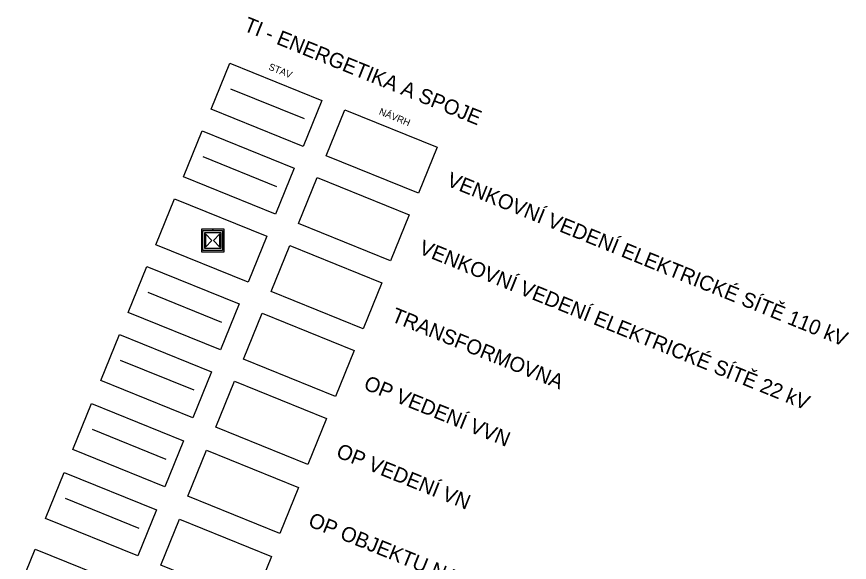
# Model space of a CAD drawing. Extents: x -522754 to -518969, y -1191121 to -1188171.
# Drawn here: x -519807 to -518969, y -1189893 to -1189344 of the extents above; entities that cross this region are included whole.
import ezdxf

# ---------------------------------------------------------------- set-up
doc = ezdxf.new("R2010")
doc.units = 0
for name, color, linetype in [('elved_110_s', 7, 'Continuous'), ('elved_22_s', 7, 'Continuous'), ('Implicitní', 7, 'Continuous'), ('ložisk_nerost', 7, 'Continuous'), ('OP_OelVN_s', 7, 'Continuous'), ('OP_VN_s', 7, 'Continuous'), ('OP_VVN_s', 7, 'Continuous'), ('plyn_VTL_s', 7, 'Continuous')]:
    doc.layers.add(name, color=color, linetype=linetype)

msp = doc.modelspace()

# ---------------------------------------------------------------- linework, layer by layer
at = {"layer": 'elved_110_s'}
msp.add_line((-519592.12, -1189416.32), (-519517.98, -1189446.37), dxfattribs=at)
at = {"layer": 'elved_22_s'}
msp.add_line((-519619.99, -1189484.54), (-519545.85, -1189514.59), dxfattribs=at)
at = {"layer": 'Implicitní'}
for points in [[(-519592.95, -1189390.41), (-519500.27, -1189427.97), (-519519.05, -1189474.31), (-519611.73, -1189436.75)], [(-519477.1, -1189437.37), (-519384.42, -1189474.93), (-519403.2, -1189521.27), (-519495.88, -1189483.7)], [(-519620.81, -1189458.64), (-519528.14, -1189496.2), (-519546.92, -1189542.54), (-519639.59, -1189504.98)], [(-519504.97, -1189505.59), (-519412.29, -1189543.15), (-519431.07, -1189589.49), (-519523.75, -1189551.93)], [(-519648.5, -1189526.95), (-519555.82, -1189564.51), (-519574.6, -1189610.85), (-519667.28, -1189573.28)], [(-519532.65, -1189573.9), (-519439.97, -1189611.46), (-519458.75, -1189657.8), (-519551.43, -1189620.24)], [(-519676.36, -1189595.17), (-519583.69, -1189632.73), (-519602.47, -1189679.07), (-519695.15, -1189641.51)], [(-519560.52, -1189642.12), (-519467.84, -1189679.68), (-519486.62, -1189726.02), (-519579.3, -1189688.46)], [(-519704.05, -1189663.48), (-519611.37, -1189701.04), (-519630.15, -1189747.38), (-519722.83, -1189709.82)], [(-519588.2, -1189710.43), (-519495.52, -1189747.99), (-519514.3, -1189794.33), (-519606.98, -1189756.77)], [(-519732.22, -1189732.99), (-519639.54, -1189770.55), (-519658.32, -1189816.89), (-519751, -1189779.32)], [(-519616.37, -1189779.94), (-519523.69, -1189817.5), (-519542.48, -1189863.84), (-519635.15, -1189826.28)], [(-519759.54, -1189802.56), (-519666.87, -1189840.12), (-519685.65, -1189886.46), (-519778.32, -1189848.9)], [(-519643.7, -1189849.51), (-519551.02, -1189887.07), (-519569.8, -1189933.41), (-519662.48, -1189895.85)], [(-519788.72, -1189879.61), (-519696.04, -1189917.17), (-519714.82, -1189963.51), (-519807.5, -1189925.95)]]:
    msp.add_lwpolyline(points, close=True, dxfattribs=at)
at = {"layer": 'ložisk_nerost'}
for p, q in [((-519610.89, -1189569.01), (-519617.5, -1189562.39)), ((-519602.85, -1189562.39), (-519609.47, -1189569.01)), ((-519617.5, -1189568.97), (-519618.2, -1189568.97)), ((-519618.2, -1189569.01), (-519617.5, -1189569.01)), ((-519617.5, -1189575.63), (-519610.89, -1189569.01)), ((-519609.47, -1189569.01), (-519602.86, -1189575.63)), ((-519602.16, -1189568.97), (-519602.86, -1189568.97)), ((-519602.86, -1189569.01), (-519602.16, -1189569.01))]:
    msp.add_line(p, q, dxfattribs=at)
for points in [[(-519610.21, -1189557.57), (-519621.62, -1189557.57), (-519621.62, -1189580.45), (-519598.74, -1189580.45), (-519598.74, -1189557.57), (-519610.18, -1189557.57)], [(-519610.18, -1189558.97), (-519600.15, -1189558.98), (-519600.15, -1189579.04), (-519620.21, -1189579.04), (-519620.21, -1189558.97), (-519610.21, -1189558.97)], [(-519620.21, -1189558.98), (-519600.15, -1189558.98), (-519600.15, -1189579.04), (-519620.21, -1189579.04), (-519620.21, -1189558.98)], [(-519618.2, -1189568.97), (-519618.2, -1189560.99), (-519610.15, -1189560.99)], [(-519617.5, -1189562.39), (-519617.5, -1189568.97)], [(-519610.21, -1189558.97), (-519610.21, -1189557.57)], [(-519610.18, -1189557.57), (-519610.18, -1189558.97)], [(-519610.15, -1189560.99), (-519602.16, -1189560.99), (-519602.16, -1189568.97)], [(-519602.86, -1189568.97), (-519602.85, -1189562.39)], [(-519610.15, -1189577.03), (-519618.2, -1189577.03), (-519618.2, -1189569.01)], [(-519617.5, -1189569.01), (-519617.5, -1189575.63)], [(-519602.16, -1189569.01), (-519602.16, -1189577.03), (-519610.15, -1189577.03)], [(-519602.86, -1189575.63), (-519602.86, -1189569.01)]]:
    msp.add_lwpolyline(points, dxfattribs=at)
at = {"layer": 'OP_OelVN_s'}
msp.add_line((-519731.4, -1189758.89), (-519657.26, -1189788.94), dxfattribs=at)
at = {"layer": 'OP_VN_s'}
msp.add_line((-519703.23, -1189689.38), (-519629.09, -1189719.43), dxfattribs=at)
at = {"layer": 'OP_VVN_s'}
msp.add_line((-519675.54, -1189621.07), (-519601.4, -1189651.12), dxfattribs=at)
at = {"layer": 'plyn_VTL_s'}
msp.add_line((-519758.72, -1189828.46), (-519684.58, -1189858.51), dxfattribs=at)

# ---------------------------------------------------------------- texts
at = {"layer": 'Implicitní'}
for s, height, p in [('TI - ENERGETIKA A SPOJE', 15, (-519580.05, -1189357.45)), ('STAV', 7, (-519554.58, -1189396.79)), ('NÁVRH', 7, (-519443.43, -1189441.84)), ('VENKOVNÍ VEDENÍ ELEKTRICKÉ SÍTĚ 110 kV', 15, (-519375.8, -1189513.49)), ('VENKOVNÍ VEDENÍ ELEKTRICKÉ SÍTĚ 22 kV', 15, (-519403.67, -1189581.71)), ('TRANSFORMOVNA', 15, (-519431.36, -1189650.02)), ('OP VEDENÍ VVN', 15, (-519459.22, -1189718.24)), ('OP VEDENÍ VN', 15, (-519486.91, -1189786.55)), ('OP OBJEKTU NA EL.SÍTI VN', 15, (-519515.08, -1189856.06))]:
    msp.add_text(s, height=height, rotation=337.93793, dxfattribs=at).set_placement(p)

doc.saveas('drawing.dxf')
